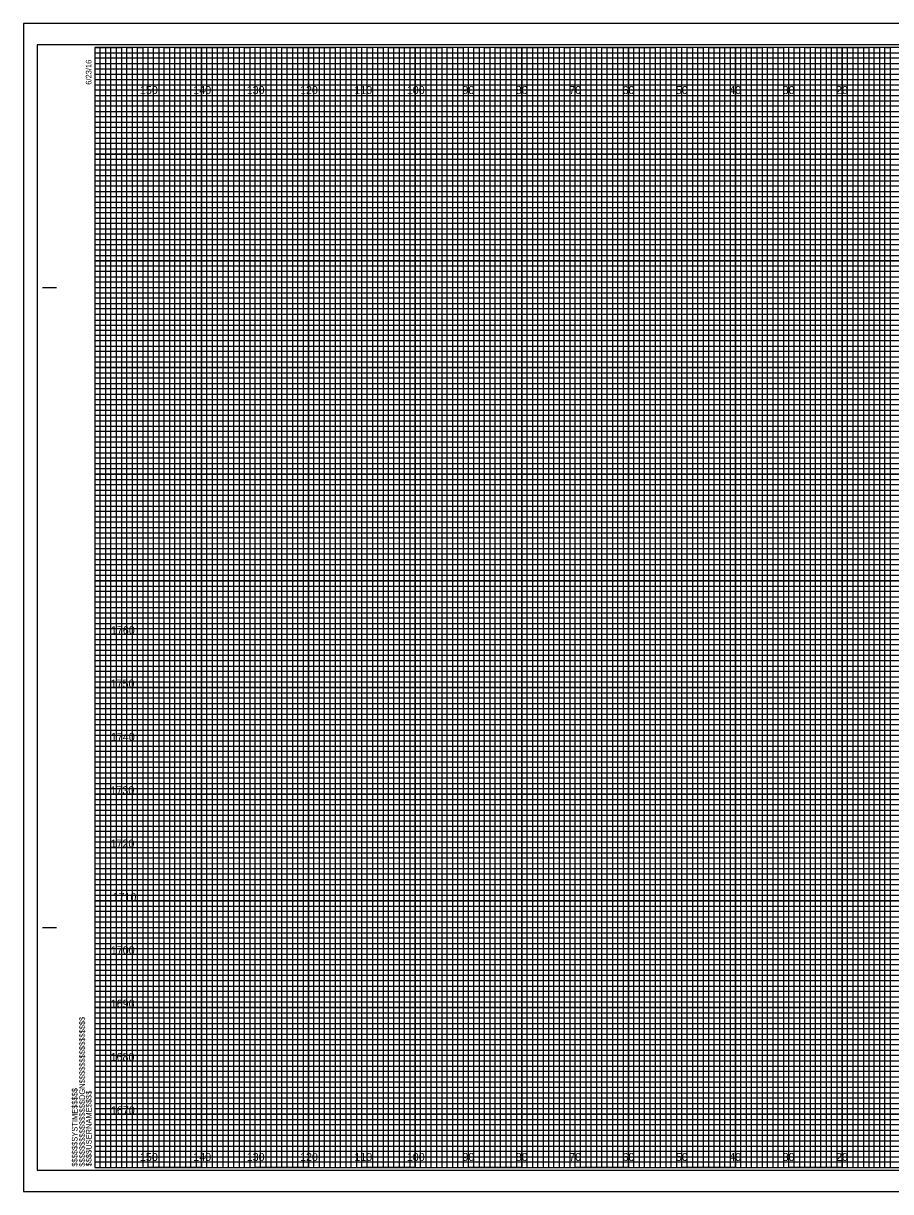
# Model space of a CAD drawing. Extents: x -419 to 4739, y -630 to 13534.
# Drawn here: x 1197.8 to 1360.3, y -20.4 to 198.6 of the extents above; entities that cross this region are included whole.
import ezdxf

# ---------------------------------------------------------------- set-up
doc = ezdxf.new("R2010")
doc.units = 0
for name, color, linetype in [('Old_Level_62', 7, 'Continuous'), ('Pattern 1', 7, 'Continuous'), ('Pattern 18', 7, 'Continuous'), ('Pattern 4', 7, 'Continuous'), ('Pattern 5', 7, 'Continuous'), ('Prop Dimension', 7, 'Continuous'), ('Prop Horizontal Alignment', 7, 'Continuous'), ('Raster_Level_0', 7, 'Continuous'), ('Scratch_Level_0', 7, 'Continuous'), ('Scratch_Level_3', 7, 'Continuous'), ('Scratch_Level_5', 7, 'Continuous')]:
    doc.layers.add(name, color=color, linetype=linetype)

msp = doc.modelspace()

# ---------------------------------------------------------------- linework, layer by layer
at = {"layer": 'Old_Level_62'}
for p, q in [((1201.42, 149.06), (1203.92, 149.06)), ((1201.52, 149.06), (1204.02, 149.06)), ((1201.42, 29.06), (1203.92, 29.06)), ((1201.52, 29.06), (1204.02, 29.06)), ((1211.22, -15.94), (1211.22, -15.94)), ((1211.22, -15.94), (1211.22, -15.94)), ((1211.22, -15.94), (1211.22, -15.94)), ((1211.22, -15.94), (1211.22, -15.94)), ((1211.22, -15.94), (1211.22, -15.94)), ((1211.22, -15.94), (1211.22, -15.94)), ((1211.22, -15.94), (1211.22, -15.94))]:
    msp.add_line(p, q, dxfattribs=at)
msp.add_lwpolyline([(1531.22, 194.06), (1211.22, 194.06), (1211.22, -15.94), (1531.22, -15.94)], close=True, dxfattribs=at)
at = {"layer": 'Pattern 18'}
msp.add_lwpolyline([(1197.82, -20.44), (1534.52, -20.44), (1534.52, 198.56), (1197.82, 198.56)], close=True, dxfattribs=at)
at = {"layer": 'Pattern 4'}
for p, q in [((1211.22, 193.06), (1471.22, 193.06)), ((1471.22, 192.04), (1211.22, 192.04)), ((1211.22, 192.04), (1211.22, 191.06)), ((1211.22, 191.06), (1471.22, 191.06)), ((1471.22, 189.95), (1211.22, 189.95)), ((1211.22, 189.95), (1211.22, 188.06)), ((1211.22, 188.06), (1531.22, 188.06))]:
    msp.add_line(p, q, dxfattribs=at)
for points in [[(1211.22, 187.06), (1481.22, 187.06), (1531.22, 187.06), (1531.22, 186.06), (1211.22, 186.06)], [(1211.22, 185.06), (1531.22, 185.06), (1531.22, 183.06), (1211.22, 183.06)], [(1211.22, 182.06), (1531.22, 182.06), (1531.22, 181.06), (1211.22, 181.04)], [(1211.22, 180.06), (1531.22, 180.06), (1531.22, 178.06), (1211.22, 178.06)], [(1211.22, 177.06), (1531.22, 177.06), (1531.22, 176.06), (1211.22, 176.06)], [(1211.22, 175.06), (1531.22, 175.06), (1531.22, 173.06), (1211.22, 173.06)], [(1211.22, 172.06), (1531.22, 172.06), (1531.22, 171.06), (1211.22, 171.06)], [(1211.22, 170.06), (1531.22, 170.06), (1531.22, 168.06), (1211.22, 168.06)], [(1211.22, 167.06), (1531.22, 167.06), (1531.22, 166.06), (1211.22, 166.06)], [(1211.22, 165.06), (1531.22, 165.06), (1531.22, 163.06), (1211.22, 163.06)], [(1211.22, 162.06), (1531.22, 162.06), (1531.22, 161.06), (1211.22, 161.06)], [(1211.22, 160.06), (1531.22, 160.06), (1531.22, 158.01), (1531.22, 157.06), (1531.22, 156.06), (1211.22, 156.06)], [(1211.22, 158.06), (1531.22, 158.06), (1531.22, 157.06), (1211.22, 157.06)], [(1211.22, 155.06), (1531.22, 155.06), (1531.22, 153.06), (1211.22, 153.09)], [(1211.22, 153.09), (1531.22, 153.06), (1531.22, 152.06), (1211.22, 152.06)], [(1211.22, 151.06), (1531.22, 151.06), (1531.22, 150.06), (1211.22, 150.06)], [(1211.22, 148.06), (1531.22, 148.06), (1531.22, 147.06), (1211.22, 147.06)], [(1211.22, 146.06), (1531.22, 146.06), (1531.22, 145.06), (1211.22, 145.06)], [(1211.15, 142.95), (1531.22, 142.95), (1531.22, 141.94), (1211.15, 141.94)], [(1211.22, 141.06), (1531.22, 141.06), (1531.22, 140.06), (1211.22, 140.06)], [(1211.22, 138.06), (1531.22, 138.06), (1531.22, 137.06), (1211.22, 137.06)], [(1211.22, 136.06), (1531.22, 136.06), (1531.22, 135.06), (1211.22, 135.06)], [(1211.22, 133.06), (1531.22, 133.06), (1531.22, 132.06), (1211.22, 132.06)], [(1211.22, 131.06), (1531.22, 131.06), (1531.22, 130.06), (1211.22, 130.06)], [(1211.22, 128.06), (1531.22, 128.06), (1531.22, 127.06), (1211.22, 127.06)], [(1211.22, 126.06), (1531.22, 126.06), (1531.22, 125.06), (1211.22, 125.06)], [(1211.22, 123.06), (1531.22, 123.06), (1531.21, 122.04), (1211.22, 122.06)], [(1211.22, 121.06), (1531.22, 121.06), (1531.22, 120.06), (1211.22, 120.06)], [(1211.22, 118.06), (1531.22, 118.06), (1531.22, 117.06), (1211.22, 117.06)], [(1211.22, 116.06), (1531.22, 116.06), (1531.22, 115.06), (1211.22, 115.06)], [(1211.22, 113.06), (1531.22, 113.06), (1531.22, 112.06), (1211.22, 112.06)], [(1211.22, 111.06), (1531.22, 111.06), (1531.22, 110.06), (1211.22, 110.06)], [(1211.22, 108.06), (1531.22, 108.06), (1531.22, 107.06), (1211.22, 107.06)], [(1211.22, 106.06), (1531.22, 106.06), (1531.22, 105.06), (1211.22, 105.06)], [(1211.22, 103.06), (1531.22, 103.06), (1531.22, 102.06), (1211.22, 102.06)], [(1211.22, 101.05), (1531.29, 100.97), (1531.22, 100.06), (1211.22, 100.06)], [(1211.22, 98.06), (1531.22, 98.06), (1531.22, 97.06), (1211.22, 97.06)], [(1211.22, 96.06), (1531.22, 96.06), (1531.22, 95.06), (1211.22, 95.06)], [(1211.22, 93.06), (1531.22, 93.06), (1531.22, 92.06), (1211.22, 92.06)], [(1211.22, 91.06), (1531.22, 91.06), (1531.22, 90.06), (1211.22, 90.06)], [(1211.22, 88.06), (1531.22, 88.06), (1531.22, 87.06), (1211.22, 87.06)], [(1211.22, 86.06), (1531.22, 86.06), (1531.22, 85.06), (1211.22, 85.06)], [(1211.22, 83.06), (1531.22, 83.06), (1531.22, 82.06), (1211.22, 82.06)], [(1211.22, 81.06), (1531.22, 81.06), (1531.22, 80.06), (1211.22, 80.06)], [(1211.22, 78.06), (1531.22, 78.06), (1531.22, 77.06), (1211.22, 77.06)], [(1211.22, 76.06), (1531.22, 76.06), (1531.22, 75.06), (1211.22, 75.06)], [(1211.22, 73.06), (1531.22, 73.06), (1531.22, 72.06), (1211.22, 72.06)], [(1211.22, 71.06), (1531.22, 71.06), (1531.22, 70.06), (1211.22, 70.06)], [(1211.22, 68.06), (1531.22, 68.06), (1531.22, 67.06), (1211.22, 67.06)], [(1211.22, 66.06), (1531.22, 66.06), (1531.22, 65.06), (1211.22, 65.06)], [(1211.22, 63.06), (1531.22, 63.06), (1531.21, 62.04), (1211.22, 62.06)], [(1211.22, 61.06), (1531.22, 61.06), (1531.22, 60.06), (1211.22, 60.06)], [(1211.22, 58.06), (1531.22, 58.06), (1531.22, 57.06), (1211.22, 57.06)], [(1211.22, 56.06), (1531.22, 56.06), (1531.22, 55.06), (1211.22, 55.06)], [(1211.22, 53.06), (1531.22, 53.06), (1531.22, 52.06), (1211.22, 52.06)], [(1211.22, 51.06), (1531.22, 51.06), (1531.22, 50.06), (1211.22, 50.06)], [(1211.22, 48.06), (1531.22, 48.06), (1531.22, 47.06), (1211.22, 47.06)], [(1211.22, 46.06), (1531.22, 46.06), (1531.22, 45.06), (1211.22, 45.06)], [(1211.22, 43.06), (1531.22, 43.06), (1531.22, 42.06), (1211.22, 42.06)], [(1211.22, 41.05), (1531.29, 40.97), (1531.22, 40.06), (1211.22, 40.06)], [(1211.22, 38.06), (1531.22, 38.06), (1531.22, 37.06), (1211.22, 37.06)], [(1211.22, 36.06), (1531.22, 36.06), (1531.22, 35.06), (1211.22, 35.06)], [(1211.22, 33.06), (1531.22, 33.06), (1531.22, 32.06), (1211.22, 32.06)], [(1211.22, 31.06), (1531.22, 31.06), (1531.22, 30.06), (1211.22, 30.06)], [(1211.22, 28.06), (1531.22, 28.06), (1531.22, 27.06), (1211.22, 27.06)], [(1211.22, 26.06), (1531.22, 26.06), (1531.22, 25.06), (1211.22, 25.06)], [(1211.22, 23.06), (1531.22, 23.06), (1531.22, 22.06), (1211.22, 22.06)], [(1211.22, 21.06), (1531.22, 21.06), (1531.22, 20.06), (1211.22, 20.06)], [(1211.22, 18.06), (1531.22, 18.06), (1531.22, 17.06), (1211.22, 17.06)], [(1211.22, 16.06), (1531.22, 16.06), (1531.22, 15.06), (1211.22, 15.06)], [(1211.22, 13.06), (1531.22, 13.06), (1531.22, 12.06), (1211.22, 12.06)], [(1211.22, 11.06), (1531.22, 11.06), (1531.22, 10.06), (1211.22, 10.06)], [(1211.22, 8.06), (1531.22, 8.06), (1531.22, 7.06), (1211.22, 7.06)], [(1211.22, 6.06), (1531.22, 6.06), (1531.22, 5.06), (1211.22, 5.06)], [(1211.22, 3.06), (1531.22, 3.06), (1531.22, 2.06), (1211.22, 2.06)], [(1211.22, 1.06), (1531.22, 1.06), (1531.22, 0.06), (1211.22, 0.06)], [(1211.22, -1.94), (1531.22, -1.94), (1531.22, -2.94), (1211.22, -2.94)], [(1211.22, -3.94), (1531.22, -3.94), (1531.22, -4.94), (1211.22, -4.94)], [(1211.22, -6.94), (1531.22, -6.94), (1531.22, -7.94), (1211.22, -7.94)], [(1211.22, -8.94), (1531.22, -8.94), (1531.22, -9.94), (1211.22, -9.94)], [(1211.22, -11.94), (1531.22, -11.94), (1531.22, -12.94), (1211.22, -12.94)], [(1211.22, -13.94), (1531.22, -13.94), (1531.22, -14.94), (1211.22, -14.94)]]:
    msp.add_lwpolyline(points, dxfattribs=at)
at = {"layer": 'Pattern 5'}
for p, q in [((1534.52, 198.56), (1197.82, 198.56)), ((1197.82, 198.56), (1197.82, -20.44)), ((1197.82, -20.44), (1534.52, -20.44))]:
    msp.add_line(p, q, dxfattribs=at)
at = {"layer": 'Prop Dimension'}
for points in [[(1211.22, -15.94), (1212.22, -15.94), (1212.22, 194.06), (1213.22, 194.06), (1213.22, -15.94)], [(1213.22, -15.94), (1214.22, -15.94), (1214.22, 194.06), (1215.22, 194.06), (1215.22, -15.94)], [(1216.22, -15.94), (1217.22, -15.94), (1217.22, 194.06), (1218.22, 194.06), (1218.22, -15.94)], [(1218.22, -15.94), (1219.22, -15.94), (1219.22, 194.06), (1220.22, 194.06), (1220.22, -15.94)], [(1221.22, -15.94), (1222.22, -15.94), (1222.22, 194.06), (1223.22, 194.06), (1223.22, -15.94)], [(1223.22, -15.94), (1224.22, -15.94), (1224.22, 194.06), (1225.22, 194.06), (1225.22, -15.94)], [(1226.22, -15.94), (1227.22, -15.94), (1227.22, 194.06), (1228.22, 194.06), (1228.22, -15.94)], [(1228.22, -15.94), (1229.22, -15.94), (1229.22, 194.06), (1230.22, 194.06), (1230.22, -15.94)], [(1231.22, -15.94), (1232.22, -15.94), (1232.22, 194.06), (1233.22, 194.06), (1233.22, -15.94)], [(1233.22, -15.94), (1234.22, -15.94), (1234.22, 194.06), (1235.22, 194.06), (1235.22, -15.94)], [(1236.22, -15.94), (1237.22, -15.94), (1237.22, 194.06), (1238.22, 194.06), (1238.22, -15.94)], [(1238.22, -15.94), (1239.22, -15.94), (1239.22, 194.06), (1240.22, 194.06), (1240.22, -15.94)], [(1241.22, -15.94), (1242.22, -15.94), (1242.22, 194.06), (1243.22, 194.06), (1243.22, -15.94)], [(1243.22, -15.94), (1244.22, -15.94), (1244.22, 194.06), (1245.22, 194.06), (1245.22, -15.94)], [(1246.22, -15.94), (1247.22, -15.94), (1247.22, 194.06), (1248.22, 194.06), (1248.22, -15.94)], [(1248.22, -15.94), (1249.22, -15.94), (1249.22, 194.06), (1250.22, 194.06), (1250.22, -15.94)], [(1251.22, -15.94), (1252.22, -15.94), (1252.22, 194.06), (1253.22, 194.06), (1253.22, -15.94)], [(1253.22, -15.94), (1254.22, -15.94), (1254.22, 194.06), (1255.22, 194.06), (1255.22, -15.94)], [(1256.22, -15.94), (1257.22, -15.94), (1257.22, 194.06), (1258.22, 194.06), (1258.22, -15.94)], [(1258.22, -15.94), (1259.22, -15.94), (1259.22, 194.06), (1260.22, 194.06), (1260.22, -15.94)], [(1261.22, -15.94), (1262.22, -15.94), (1262.22, 194.06), (1263.22, 194.06), (1263.22, -15.94)], [(1263.22, -15.94), (1264.22, -15.94), (1264.22, 194.06), (1265.22, 194.06), (1265.22, -15.94)], [(1266.22, -15.94), (1267.22, -15.94), (1267.22, 194.06), (1268.22, 194.06), (1268.22, -15.94)], [(1268.22, -15.94), (1269.22, -15.94), (1269.22, 194.06), (1270.22, 194.06), (1270.22, -15.94)], [(1271.22, -15.94), (1272.22, -15.94), (1272.22, 194.06), (1273.22, 194.06), (1273.22, -15.94)], [(1273.22, -15.94), (1274.22, -15.94), (1274.22, 194.06), (1275.22, 194.06), (1275.22, -15.94)], [(1276.22, -15.94), (1277.22, -15.94), (1277.22, 194.06), (1278.22, 194.06), (1278.22, -15.94)], [(1278.22, -15.94), (1279.22, -15.94), (1279.22, 194.06), (1280.22, 194.06), (1280.22, -15.94)], [(1281.22, -15.94), (1282.22, -15.94), (1282.22, 194.06), (1283.22, 194.06), (1283.22, -15.94)], [(1283.22, -15.94), (1284.22, -15.94), (1284.22, 194.06), (1285.22, 194.06), (1285.22, -15.94)], [(1286.22, -15.94), (1287.22, -15.94), (1287.22, 194.06), (1288.22, 194.06), (1288.22, -15.94)], [(1288.22, -15.94), (1289.22, -15.94), (1289.22, 194.06), (1290.22, 194.06), (1290.22, -15.94)], [(1291.22, -15.94), (1292.22, -15.94), (1292.22, 194.06), (1293.22, 194.06), (1293.22, -15.94)], [(1293.22, -15.94), (1294.22, -15.94), (1294.22, 194.06), (1295.22, 194.06), (1295.22, -15.94)], [(1296.22, -15.94), (1297.22, -15.94), (1297.22, 194.06), (1298.22, 194.06), (1298.22, -15.94)], [(1298.22, -15.94), (1299.22, -15.94), (1299.22, 194.06), (1300.22, 194.06), (1300.22, -15.94)], [(1301.22, -15.94), (1302.22, -15.94), (1302.22, 194.06), (1303.22, 194.06), (1303.22, -15.94)], [(1303.22, -15.94), (1304.22, -15.94), (1304.22, 194.06), (1305.22, 194.06), (1305.22, -15.94)], [(1306.22, -15.94), (1307.22, -15.94), (1307.22, 194.06), (1308.22, 194.06), (1308.22, -15.94)], [(1308.22, -15.94), (1309.22, -15.94), (1309.22, 194.06), (1310.22, 194.06), (1310.22, -15.94)], [(1311.22, -15.94), (1312.22, -15.94), (1312.22, 194.06), (1313.22, 194.06), (1313.22, -15.94)], [(1313.22, -15.94), (1314.22, -15.94), (1314.22, 194.06), (1315.22, 194.06), (1315.22, -15.94)], [(1316.22, -15.94), (1317.22, -15.94), (1317.22, 194.06), (1318.22, 194.06), (1318.22, -15.94)], [(1318.22, -15.94), (1319.22, -15.94), (1319.22, 194.06), (1320.22, 194.06), (1320.22, -15.94)], [(1321.22, -15.94), (1322.22, -15.94), (1322.22, 194.06), (1323.22, 194.06), (1323.22, -15.94)], [(1323.22, -15.94), (1324.22, -15.94), (1324.22, 194.06), (1325.22, 194.06), (1325.22, -15.94)], [(1326.22, -15.94), (1327.22, -15.94), (1327.22, 194.06), (1328.22, 194.06), (1328.22, -15.94)], [(1328.22, -15.94), (1329.22, -15.94), (1329.22, 194.06), (1330.22, 194.06), (1330.22, -15.94)], [(1331.22, -15.94), (1332.22, -15.94), (1332.22, 194.06), (1333.22, 194.06), (1333.22, -15.94)], [(1333.22, -15.94), (1334.22, -15.94), (1334.22, 194.06), (1335.22, 194.06), (1335.22, -15.94)], [(1336.22, -15.94), (1337.22, -15.94), (1337.22, 194.06), (1338.22, 194.06), (1338.22, -15.94)], [(1338.22, -15.94), (1339.22, -15.94), (1339.22, 194.06), (1340.22, 194.06), (1340.22, -15.94)], [(1341.22, -15.94), (1342.22, -15.94), (1342.22, 194.06), (1343.22, 194.06), (1343.22, -15.94)], [(1343.22, -15.94), (1344.22, -15.94), (1344.22, 194.06), (1345.22, 194.06), (1345.22, -15.94)], [(1346.22, -15.94), (1347.22, -15.94), (1347.22, 194.06), (1348.22, 194.06), (1348.22, -15.94)], [(1348.22, -15.94), (1349.22, -15.94), (1349.22, 194.06), (1350.22, 194.06), (1350.22, -15.94)], [(1351.22, -15.94), (1352.22, -15.94), (1352.22, 194.06), (1353.22, 194.06), (1353.22, -15.94)], [(1353.22, -15.94), (1354.22, -15.94), (1354.22, 194.06), (1355.22, 194.06), (1355.22, -15.94)], [(1356.22, -15.94), (1357.22, -15.94), (1357.22, 194.06), (1358.22, 194.06), (1358.22, -15.94)], [(1358.22, -15.94), (1359.22, -15.94), (1359.22, 194.06), (1360.22, 194.06), (1360.22, -15.94)]]:
    msp.add_lwpolyline(points, dxfattribs=at)
at = {"layer": 'Prop Horizontal Alignment'}
for points in [[(1211.22, 194.06), (1216.22, 194.06), (1216.22, -15.94), (1226.22, -15.94), (1226.22, 194.06), (1236.22, 194.06), (1236.22, -15.94), (1246.22, -15.94), (1246.22, 194.06), (1256.22, 194.06), (1256.22, -15.94), (1266.22, -15.94), (1266.22, 194.06), (1276.22, 194.06), (1276.22, -15.94), (1286.22, -15.94), (1286.22, 194.06), (1296.22, 194.06), (1296.22, -15.94), (1306.22, -15.94), (1306.22, 194.06), (1316.22, 194.06), (1316.22, -15.94), (1326.22, -15.94), (1326.22, 194.06), (1336.22, 194.06), (1336.22, -15.94), (1346.22, -15.94), (1346.22, 194.06), (1356.22, 194.06), (1356.22, -15.94), (1366.22, -15.94)], [(1211.22, 189.06), (1486.22, 189.06)], [(1211.22, 169.06), (1531.22, 169.06), (1531.22, 179.06), (1211.22, 179.06)], [(1211.22, 149.06), (1531.22, 149.06), (1531.22, 159.06), (1211.22, 159.06)], [(1211.22, 129.06), (1531.22, 129.06), (1531.22, 139.06), (1211.22, 139.06)], [(1211.22, 109.06), (1531.22, 109.06), (1531.22, 119.06), (1211.22, 119.06)], [(1211.22, 89.06), (1531.22, 89.06), (1531.22, 99.06), (1211.22, 99.06)], [(1211.22, 69.06), (1531.22, 69.06), (1531.22, 79.06), (1211.22, 79.06)], [(1211.22, 49.06), (1531.22, 49.06), (1531.22, 59.06), (1211.22, 59.06)], [(1211.22, 29.06), (1531.22, 29.06), (1531.22, 39.06), (1211.22, 39.06)], [(1211.22, 9.06), (1531.22, 9.06), (1531.22, 19.06), (1211.22, 19.06)], [(1211.22, -10.94), (1531.22, -10.94), (1531.22, -0.94), (1211.22, -0.94)]]:
    msp.add_lwpolyline(points, dxfattribs=at)
at = {"layer": 'Scratch_Level_0'}
for p, q in [((1221.22, -15.94), (1221.22, 194.06)), ((1231.22, -15.94), (1231.22, 194.06)), ((1241.22, -15.94), (1241.22, 194.06)), ((1251.22, -15.94), (1251.22, 194.06)), ((1261.22, -15.94), (1261.22, 194.06)), ((1271.22, -15.94), (1271.22, 194.06)), ((1281.22, -15.94), (1281.22, 194.06)), ((1291.22, -15.94), (1291.22, 194.06)), ((1301.22, -15.94), (1301.22, 194.06)), ((1311.22, -15.94), (1311.22, 194.06)), ((1321.22, -15.94), (1321.22, 194.06)), ((1331.22, -15.94), (1331.22, 194.06)), ((1341.22, -15.94), (1341.22, 194.06)), ((1351.22, -15.94), (1351.22, 194.06)), ((1211.22, 184.06), (1531.22, 184.06)), ((1211.22, 174.06), (1531.22, 174.06)), ((1211.22, 164.06), (1531.22, 164.06)), ((1211.22, 154.06), (1531.22, 154.06)), ((1211.22, 144.06), (1531.22, 144.06)), ((1211.22, 134.06), (1531.22, 134.06)), ((1211.22, 124.06), (1531.22, 124.06)), ((1211.22, 114.06), (1531.22, 114.06)), ((1211.22, 104.06), (1531.22, 104.06)), ((1211.22, 94.06), (1531.22, 94.06)), ((1211.22, 84.06), (1531.22, 84.06)), ((1211.22, 74.06), (1531.22, 74.06)), ((1211.22, 64.06), (1531.22, 64.06)), ((1211.22, 54.06), (1531.22, 54.06)), ((1211.22, 44.06), (1531.22, 44.06)), ((1211.22, 34.06), (1531.22, 34.06)), ((1211.22, 24.06), (1531.22, 24.06)), ((1211.22, 14.06), (1531.22, 14.06)), ((1211.22, 4.06), (1531.22, 4.06)), ((1211.22, -5.94), (1531.22, -5.94))]:
    msp.add_line(p, q, dxfattribs=at)
at = {"layer": 'Scratch_Level_3'}
for p, q in [((1221.22, 194.06), (1211.22, 194.06)), ((1221.22, -15.94), (1221.22, 194.06)), ((1241.22, 194.06), (1231.22, 194.06)), ((1231.22, 194.06), (1231.22, -15.94)), ((1241.22, -15.94), (1241.22, 194.06)), ((1261.22, 194.06), (1251.22, 194.06)), ((1251.22, 194.06), (1251.22, -15.94)), ((1261.22, -15.94), (1261.22, 194.06)), ((1281.22, 194.06), (1271.22, 194.06)), ((1271.22, 194.06), (1271.22, -15.94)), ((1281.22, -15.94), (1281.22, 194.06)), ((1301.22, 194.06), (1291.22, 194.06)), ((1291.22, 194.06), (1291.22, -15.94)), ((1301.22, -15.94), (1301.22, 194.06)), ((1321.22, 194.06), (1311.22, 194.06)), ((1311.22, 194.06), (1311.22, -15.94)), ((1321.22, -15.94), (1321.22, 194.06)), ((1341.22, 194.06), (1331.22, 194.06)), ((1331.22, 194.06), (1331.22, -15.94)), ((1341.22, -15.94), (1341.22, 194.06)), ((1361.22, 194.06), (1351.22, 194.06)), ((1351.22, 194.06), (1351.22, -15.94)), ((1231.22, -15.94), (1221.22, -15.94)), ((1251.22, -15.94), (1241.22, -15.94)), ((1271.22, -15.94), (1261.22, -15.94)), ((1291.22, -15.94), (1281.22, -15.94)), ((1311.22, -15.94), (1301.22, -15.94)), ((1331.22, -15.94), (1321.22, -15.94)), ((1351.22, -15.94), (1341.22, -15.94))]:
    msp.add_line(p, q, dxfattribs=at)
for points in [[(1211.22, 184.06), (1531.22, 184.06), (1531.22, 174.06), (1211.22, 174.06)], [(1211.22, 164.06), (1531.22, 164.06), (1531.22, 154.06), (1211.22, 154.06)], [(1211.22, 144.06), (1531.22, 144.06), (1531.22, 134.06), (1211.22, 134.06)], [(1211.22, 124.06), (1531.22, 124.06), (1531.22, 114.06), (1211.22, 114.06)], [(1211.22, 104.06), (1531.22, 104.06), (1531.22, 94.06), (1211.22, 94.06)], [(1211.22, 84.06), (1531.22, 84.06), (1531.22, 74.06), (1211.22, 74.06)], [(1211.22, 64.06), (1531.22, 64.06), (1531.22, 54.06), (1211.22, 54.06)], [(1211.22, 44.06), (1531.22, 44.06), (1531.22, 34.06), (1211.22, 34.06)], [(1211.22, 24.06), (1531.22, 24.06), (1531.22, 14.06), (1211.22, 14.06)], [(1211.22, 4.06), (1531.22, 4.06), (1531.22, -5.94), (1211.22, -5.94)]]:
    msp.add_lwpolyline(points, dxfattribs=at)
at = {"layer": 'Scratch_Level_5'}
msp.add_lwpolyline([(1200.42, -16.44), (1533.62, -16.44), (1533.62, 194.56), (1200.42, 194.56)], close=True, dxfattribs=at)

# ---------------------------------------------------------------- texts
at = {"layer": 'Old_Level_62'}
for s, p in [('6/23/16', (1210.57, 187.06)), ('$$$$$$$$$$$$$$$$DGN$$$$$$$$$$$$$$$$', (1209.34, -15.76)), ('$$$$$$SYSTIME$$$$$', (1207.96, -15.76)), ('$$$$USERNAME$$$$', (1210.6, -15.71))]:
    msp.add_text(s, height=1.05, rotation=90, dxfattribs=at).set_placement(p)
at = {"layer": 'Pattern 1'}
for s, p in [('1760', (1214.22, 84.06)), ('1750', (1214.17, 74.06)), ('1740', (1214.22, 64.06)), ('1730', (1214.14, 54.06)), ('1720', (1214.15, 44.06)), ('1710', (1214.53, 34.06)), ('1700', (1214.2, 24.06)), ('1690', (1214.19, 14.06)), ('1680', (1214.16, 4.06)), ('1670', (1214.22, -5.94))]:
    msp.add_text(s, height=1.5, dxfattribs=at).set_placement(p)
at = {"layer": 'Raster_Level_0'}
for s, p in [('150', (1219.66, 185.31)), ('140', (1229.66, 185.31)), ('130', (1239.66, 185.31)), ('120', (1249.66, 185.31)), ('110', (1259.84, 185.31)), ('100', (1269.66, 185.31)), ('90', (1280.08, 185.31)), ('80', (1290.08, 185.31)), ('70', (1300.08, 185.31)), ('60', (1310.08, 185.31)), ('50', (1320.08, 185.31)), ('40', (1330.08, 185.31)), ('30', (1340.08, 185.31)), ('20', (1350.08, 185.31)), ('150', (1219.66, -14.69)), ('140', (1229.66, -14.69)), ('130', (1239.66, -14.69)), ('120', (1249.66, -14.69)), ('110', (1259.84, -14.69)), ('100', (1269.66, -14.69)), ('90', (1280.08, -14.69)), ('80', (1290.08, -14.69)), ('70', (1300.08, -14.69)), ('60', (1310.08, -14.69)), ('50', (1320.08, -14.69)), ('40', (1330.08, -14.69)), ('30', (1340.08, -14.69)), ('20', (1350.08, -14.69))]:
    msp.add_text(s, height=1.5, dxfattribs=at).set_placement(p)

doc.saveas('drawing.dxf')
